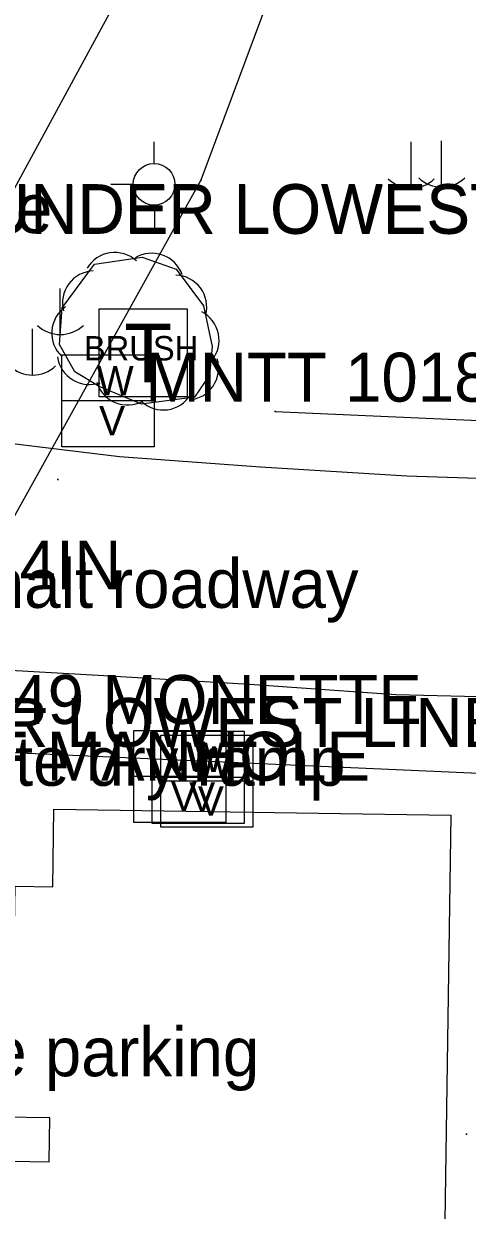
# Model space of a CAD drawing. Extents: x 1802180 to 1804859, y 572524 to 575172.
# Drawn here: x 1803453.9 to 1803499.2, y 573469.6 to 573590.8 of the extents above; entities that cross this region are included whole.
import ezdxf

# ---------------------------------------------------------------- set-up
doc = ezdxf.new("R2010")
doc.units = 0
for name, color, linetype in [('S_BUILDING', 7, 'Continuous'), ('S_EDGE_PAVEMENT', 7, 'Continuous'), ('S_ELECTRIC_UTILITIES_ANNOT', 7, 'Continuous'), ('S_GAS_UTILITIES', 7, 'Continuous'), ('S_MANHOLE_ANNOT', 7, 'Continuous'), ('S_MSC_PT_SYM', 7, 'Continuous'), ('S_PRIMARY_CTL_ANNOT', 7, 'Continuous'), ('S_SANITARY_SEWER', 7, 'Continuous'), ('S_SANITARY_SEWER_ANNOT', 7, 'Continuous'), ('S_SURVEY_TEXT_ANNOT', 7, 'Continuous'), ('S_TELEPHONE_UTILITIES', 7, 'Continuous'), ('S_TELEPHONE_UTILITIES_ANNOT', 7, 'Continuous'), ('S_TREE', 7, 'Continuous'), ('S_TREE_ANNOT', 7, 'Continuous'), ('S_UTILITY_POLE', 7, 'Continuous'), ('S_UTL_PT_SYM', 7, 'Continuous'), ('S_WATER_UTILITIES', 7, 'Continuous')]:
    doc.layers.add(name, color=color, linetype=linetype)

msp = doc.modelspace()

# ---------------------------------------------------------------- linework, layer by layer
at = {"layer": 'S_BUILDING'}
msp.add_lwpolyline([(1803497.51, 573509.97), (1803496.23, 573422.39), (1803450.6, 573423.06), (1803450.76, 573433.49), (1803451.68, 573433.48), (1803451.88, 573446.54), (1803455.91, 573446.48), (1803455.98, 573451.08), (1803451.11, 573451.15), (1803451.27, 573461.87), (1803452.31, 573461.85), (1803452.49, 573474.6), (1803456.46, 573474.55), (1803456.53, 573479.03), (1803451.72, 573479.1), (1803451.89, 573490.32), (1803452.79, 573490.31), (1803452.97, 573502.7), (1803456.82, 573502.65), (1803456.94, 573510.56), (1803497.51, 573509.97)], dxfattribs=at)
at = {"layer": 'S_EDGE_PAVEMENT'}
for points in [[(1803582.65, 573542.6), (1803567.66, 573543.2), (1803552.61, 573543), (1803537.67, 573543.31), (1803522.67, 573543.71), (1803507.51, 573544.13), (1803493.02, 573544.59), (1803478.05, 573545.52), (1803463.63, 573546.59), (1803448.74, 573548.37), (1803434.83, 573550.8), (1803427.57, 573552.87), (1803422.79, 573558.55), (1803415.14, 573571.57)], [(1803404.7, 573526.53), (1803410.04, 573527.81), (1803415.85, 573527.39), (1803431.14, 573525.87), (1803446.47, 573525.13), (1803461.46, 573524.28), (1803476.93, 573523.34), (1803491.89, 573522.3), (1803507.37, 573521.9), (1803522.19, 573522.06), (1803537.19, 573521.66), (1803552.25, 573521.68), (1803567.21, 573521.92), (1803582.21, 573521.63)]]:
    msp.add_lwpolyline(points, dxfattribs=at)
at = {"layer": 'S_GAS_UTILITIES'}
msp.add_line((1803444.32, 573558.2), (1803481.41, 573626.54), dxfattribs=at)
at = {"layer": 'S_MSC_PT_SYM'}
msp.add_lwpolyline([(1803499.14, 573477.37), (1803499.14, 573477.42), (1803499.14, 573477.37), (1803499.09, 573477.37), (1803499.14, 573477.37), (1803499.14, 573477.32), (1803499.14, 573477.37), (1803499.19, 573477.37)], dxfattribs=at)
at = {"layer": 'S_SANITARY_SEWER'}
msp.add_line((1803415.94, 573517.99), (1803600.21, 573509.85), dxfattribs=at)
at = {"layer": 'S_TELEPHONE_UTILITIES'}
msp.add_lwpolyline([(1803461.56, 573552.69), (1803461.56, 573561.69), (1803470.56, 573561.69), (1803470.56, 573552.69)], close=True, dxfattribs=at)
at = {"layer": 'S_TREE'}
msp.add_lwpolyline([(1803465.9, 573551.96), (1803461.58, 573553.75), (1803459.07, 573555.27), (1803457.52, 573558.04), (1803457.78, 573561.8), (1803461.1, 573566.27), (1803465.97, 573566.99), (1803469.45, 573565.75), (1803472.25, 573562.01), (1803473.11, 573557.84), (1803472.85, 573554.92), (1803471.33, 573552.68), (1803465.9, 573551.96)], dxfattribs=at)
for centre, start, end in [((1803463.15, 573564.17), 47.6238, 149.2207), ((1803466.95, 573564.09), 19.6948, 121.2917), ((1803461.1, 573562.29), 92.6238, 194.2207), ((1803469.28, 573561.86), 346.0225, 87.6195), ((1803460.01, 573559.22), 125.2573, 226.8542), ((1803470.53, 573558.48), 320.8036, 62.4005), ((1803460.56, 573557.25), 188.0641, 289.661), ((1803470.49, 573555.66), 274.9852, 16.5821), ((1803464.47, 573555.16), 196.7427, 298.3396), ((1803468.12, 573554.65), 226.7994, 328.3964)]:
    msp.add_arc(centre, 3.29, start, end, dxfattribs=at)
at = {"layer": 'S_UTILITY_POLE'}
for p, q in [((1803467.18, 573576.53), (1803467.18, 573578.78)), ((1803493.42, 573578.75), (1803493.42, 573574.02)), ((1803496.52, 573578.85), (1803496.52, 573574.13)), ((1803465.09, 573574.4), (1803462.76, 573574.4)), ((1803467.26, 573569.98), (1803467.26, 573572.31)), ((1803457.53, 573563.78), (1803457.53, 573559.06)), ((1803454.7, 573559.64), (1803454.7, 573554.91))]:
    msp.add_line(p, q, dxfattribs=at)
msp.add_circle((1803467.18, 573574.42), 2.13, dxfattribs=at)
for centre in [(1803493.48, 573577.45), (1803496.59, 573577.55), (1803457.6, 573562.48), (1803454.76, 573558.34)]:
    msp.add_arc(centre, 3.41, 226.3972, 313.6028, dxfattribs=at)
at = {"layer": 'S_UTL_PT_SYM'}
for points in [[(1803472, 573574.88), (1803472, 573574.93), (1803472, 573574.88), (1803471.95, 573574.88), (1803472, 573574.88), (1803472, 573574.83), (1803472, 573574.88), (1803472.05, 573574.88)], [(1803479.56, 573551.22), (1803479.56, 573551.27), (1803479.56, 573551.22), (1803479.51, 573551.22), (1803479.56, 573551.22), (1803479.56, 573551.17), (1803479.56, 573551.22), (1803479.61, 573551.22)], [(1803457.35, 573544.27), (1803457.35, 573544.32), (1803457.35, 573544.27), (1803457.3, 573544.27), (1803457.35, 573544.27), (1803457.35, 573544.22), (1803457.35, 573544.27), (1803457.4, 573544.27)]]:
    msp.add_lwpolyline(points, dxfattribs=at)
at = {"layer": 'S_WATER_UTILITIES'}
for p, q in [((1803472, 573574.88), (1803529.9, 573730.17)), ((1803399.02, 573443.59), (1803472, 573574.88)), ((1803457.76, 573557), (1803467.18, 573557)), ((1803457.76, 573547.59), (1803457.76, 573557)), ((1803467.18, 573557), (1803467.18, 573547.59)), ((1803457.76, 573552.32), (1803467.18, 573552.32)), ((1803479.56, 573551.22), (1803504.74, 573550.09)), ((1803467.18, 573547.59), (1803457.76, 573547.59)), ((1803465.1, 573518.62), (1803474.52, 573518.62)), ((1803465.1, 573509.21), (1803465.1, 573518.62)), ((1803466.97, 573518.54), (1803476.39, 573518.54)), ((1803466.97, 573509.12), (1803466.97, 573518.54)), ((1803474.52, 573518.62), (1803474.52, 573509.21)), ((1803476.39, 573518.54), (1803476.39, 573509.12)), ((1803467.86, 573518.14), (1803477.28, 573518.14)), ((1803467.86, 573508.72), (1803467.86, 573518.14)), ((1803477.28, 573518.14), (1803477.28, 573508.72)), ((1803465.1, 573513.93), (1803474.52, 573513.93)), ((1803466.97, 573513.85), (1803476.39, 573513.85)), ((1803467.86, 573513.45), (1803477.28, 573513.45)), ((1803474.52, 573509.21), (1803465.1, 573509.21)), ((1803476.39, 573509.12), (1803466.97, 573509.12)), ((1803477.28, 573508.72), (1803467.86, 573508.72))]:
    msp.add_line(p, q, dxfattribs=at)

# ---------------------------------------------------------------- texts
at = {"layer": 'S_ELECTRIC_UTILITIES_ANNOT'}
msp.add_text('lowest telephone line ', height=5, dxfattribs=at).set_placement((1803394.33, 573569.45))
at = {"layer": 'S_MANHOLE_ANNOT'}
msp.add_text('BOTTOM OF MANHOLE', height=5, dxfattribs=at).set_placement((1803414.59, 573513.48))
at = {"layer": 'S_PRIMARY_CTL_ANNOT'}
msp.add_text('PD:CUT SQ SE COR CONC PAD 49 MONETTE', height=5, dxfattribs=at).set_placement((1803349.68, 573519.28))
at = {"layer": 'S_SANITARY_SEWER_ANNOT'}
msp.add_text('HIGH PRESSURE SEWER  PLASTIC 4IN ', height=5, dxfattribs=at).set_placement((1803338.26, 573533.02))
at = {"layer": 'S_SURVEY_TEXT_ANNOT'}
for s, p in [('POINT ON ROAD UNDER LOWEST LINE ', (1803394.33, 573569.44)), ('POINT ON ROAD UNDER LOWEST LINE ', (1803394.37, 573569.36)), ('asphalt roadway', (1803439.4, 573531.14)), ('POINT ON ROAD UNDER LOWEST LINE ', (1803377.24, 573516.93)), ('concrete dry ramp', (1803432.88, 573512.96)), ('concrete parking', (1803428.51, 573483.28))]:
    msp.add_text(s, height=5, dxfattribs=at).set_placement(p)
at = {"layer": 'S_TELEPHONE_UTILITIES'}
msp.add_text('T', height=6, rotation=360, dxfattribs=at).set_placement((1803464.12, 573554.19))
at = {"layer": 'S_TELEPHONE_UTILITIES_ANNOT'}
msp.add_text('MNTT 10181 ', height=5, dxfattribs=at).set_placement((1803466.28, 573552.21))
at = {"layer": 'S_TREE_ANNOT'}
msp.add_text('BRUSH', height=2.5, dxfattribs=at).set_placement((1803460, 573556.42))
at = {"layer": 'S_WATER_UTILITIES'}
for s, p in [('W', (1803461.31, 573552.85)), ('V', (1803461.55, 573548.78)), ('W', (1803468.65, 573514.46)), ('W', (1803470.52, 573514.38)), ('W', (1803471.41, 573513.98)), ('V', (1803468.89, 573510.4)), ('V', (1803470.76, 573510.32)), ('V', (1803471.65, 573509.92))]:
    msp.add_text(s, height=3, rotation=360, dxfattribs=at).set_placement(p)

doc.saveas('drawing.dxf')
